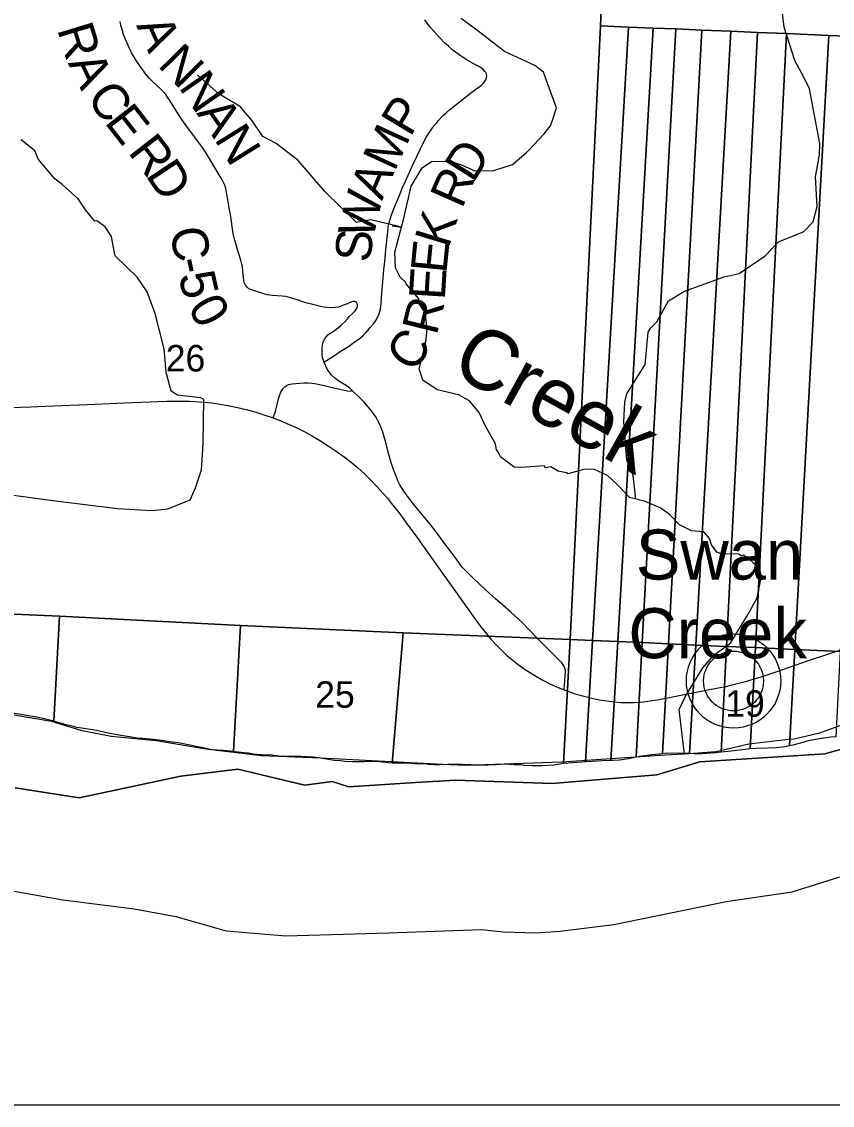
# Model space of a CAD drawing. Extents: x 396.2 to 468.4, y 232.6 to 279.1.
# Drawn here: x 422.381 to 423.66, y 264.258 to 265.969 of the extents above; entities that cross this region are included whole.
import ezdxf

# ---------------------------------------------------------------- set-up
doc = ezdxf.new("R2010")
doc.units = 0
for name, color, linetype in [('GM_X_County_Road', 7, 'Continuous'), ('GM_X_County_Road_Text', 7, 'Continuous'), ('GM_X_Major_River', 7, 'Continuous'), ('GM_X_Minor_River', 7, 'Continuous'), ('GM_X_Minor_River_Text', 7, 'Continuous'), ('GM_X_Section', 7, 'Continuous'), ('GM_X_Section_Text', 7, 'Continuous'), ('GM_X_State_Route', 7, 'Continuous'), ('GM_X_Township', 7, 'Continuous'), ('GM_X_Unincorporated', 7, 'Continuous'), ('GM_X_Unincorporated_Location', 7, 'Continuous'), ('GM_X_Unincorporated_Text', 7, 'Continuous'), ('SH_Cut_Line', 7, 'Continuous'), ('TX_P_1', 7, 'Continuous')]:
    doc.layers.add(name, color=color, linetype=linetype)

msp = doc.modelspace()

# ---------------------------------------------------------------- linework, layer by layer
at = {"layer": 'GM_X_County_Road'}
for points in [[(422.8581, 265.4314), (422.8568, 265.4354), (422.8558, 265.4388), (422.8553, 265.443), (422.8552, 265.4474), (422.8552, 265.4524), (422.8558, 265.4587), (422.8569, 265.4626), (422.8578, 265.4653), (422.8598, 265.469), (422.8621, 265.4718), (422.8642, 265.4742), (422.8673, 265.4766), (422.8727, 265.4804), (422.8774, 265.4833), (422.8809, 265.4858), (422.8851, 265.4894), (422.8907, 265.4949), (422.8953, 265.4998), (422.8979, 265.5032), (422.9024, 265.5074), (422.9066, 265.5115), (422.9089, 265.5143), (422.9103, 265.5169), (422.9108, 265.5191), (422.9109, 265.5207), (422.9107, 265.5225), (422.91, 265.5242), (422.909, 265.5255), (422.9076, 265.5265), (422.9059, 265.5271), (422.904, 265.5271), (422.9017, 265.5265), (422.8986, 265.5253), (422.8935, 265.5227), (422.8874, 265.5204), (422.8808, 265.5182), (422.8749, 265.5173), (422.8684, 265.5168), (422.8584, 265.5179), (422.8523, 265.519), (422.8402, 265.522), (422.8295, 265.525), (422.8139, 265.53), (422.8053, 265.5329), (422.7978, 265.5348), (422.7918, 265.5356), (422.7765, 265.5364), (422.7722, 265.5368), (422.7682, 265.5376), (422.7632, 265.539), (422.7481, 265.5438), (422.7426, 265.5457), (422.7394, 265.5472), (422.7365, 265.5496), (422.7342, 265.5525), (422.7331, 265.5548), (422.732, 265.5572), (422.7313, 265.5602), (422.7307, 265.5653), (422.7299, 265.5745), (422.7291, 265.5823), (422.7284, 265.5858), (422.7267, 265.5922), (422.7225, 265.6056), (422.7182, 265.62), (422.7162, 265.6277), (422.7148, 265.6345), (422.7133, 265.6447), (422.7113, 265.6581), (422.7103, 265.6641), (422.7083, 265.6743), (422.707, 265.6812), (422.7057, 265.6905), (422.7043, 265.6995), (422.703, 265.7055), (422.7014, 265.7104), (422.6999, 265.7138), (422.6966, 265.7203), (422.6854, 265.7389), (422.676, 265.7543), (422.6708, 265.7627), (422.6661, 265.7701), (422.6599, 265.7786), (422.654, 265.7865), (422.6424, 265.8018), (422.6364, 265.8105), (422.6317, 265.8175), (422.6174, 265.8399), (422.6137, 265.8456), (422.611, 265.8496), (422.6081, 265.8538), (422.6041, 265.8584), (422.5997, 265.8627), (422.588, 265.8738), (422.5828, 265.8791), (422.577, 265.8858), (422.5714, 265.893), (422.5635, 265.9044), (422.5582, 265.9127), (422.5544, 265.9196), (422.5494, 265.9298), (422.5447, 265.9406), (422.5417, 265.9486), (422.5392, 265.9565), (422.5374, 265.9628), (422.5361, 265.969)], [(422.8581, 265.4314), (422.859, 265.432), (422.8619, 265.4337), (422.8727, 265.4407), (422.8853, 265.4489), (422.8964, 265.4562), (422.9035, 265.461), (422.9089, 265.4648), (422.9133, 265.468), (422.9161, 265.4703), (422.9201, 265.474), (422.9233, 265.4772), (422.9273, 265.4813), (422.931, 265.4858), (422.9354, 265.4913), (422.9399, 265.4972), (422.9427, 265.5026), (422.9449, 265.5074), (422.946, 265.511), (422.9469, 265.5149), (422.9477, 265.5195), (422.948, 265.5232), (422.9487, 265.5331), (422.9495, 265.5462), (422.9513, 265.5639), (422.9526, 265.5773), (422.9538, 265.5897), (422.9552, 265.6035), (422.9575, 265.6278), (422.9585, 265.6369), (422.9594, 265.6432), (422.96, 265.6473), (422.9609, 265.6512), (422.9636, 265.6607), (422.9669, 265.6705), (422.9716, 265.682), (422.9775, 265.6959), (422.9792, 265.6999), (422.9821, 265.7067), (422.9867, 265.7169), (422.9977, 265.7415), (423.005, 265.757), (423.0103, 265.768), (423.0184, 265.7842), (423.0226, 265.7913), (423.0279, 265.7994), (423.032, 265.8048), (423.0348, 265.808), (423.0387, 265.8128), (423.0434, 265.8181), (423.0467, 265.8213), (423.0506, 265.825), (423.0563, 265.8298), (423.0601, 265.8329), (423.0644, 265.8364), (423.0706, 265.8413), (423.0844, 265.8521), (423.0934, 265.8588), (423.1021, 265.8653), (423.1065, 265.8687), (423.1091, 265.8709), (423.1114, 265.8736), (423.1133, 265.8769), (423.1144, 265.8798), (423.1148, 265.883), (423.1143, 265.8861), (423.1132, 265.8883), (423.112, 265.89), (423.1097, 265.8926), (423.1067, 265.8953), (423.1032, 265.8976), (423.0973, 265.9008), (423.0837, 265.9081), (423.0729, 265.9151), (423.062, 265.923), (423.0542, 265.9299), (423.0486, 265.9348), (423.0398, 265.9443), (423.0267, 265.9591), (423.021, 265.9665), (423.0172, 265.9715)], [(422.9025, 265.3864), (422.9008, 265.3879), (422.8985, 265.3901), (422.8936, 265.3937), (422.891, 265.3953), (422.8856, 265.3984), (422.8799, 265.4022), (422.8746, 265.4065), (422.87, 265.4108), (422.8661, 265.4158), (422.8632, 265.4204), (422.8614, 265.4238), (422.8599, 265.4268), (422.8587, 265.4299), (422.8581, 265.4314)], [(422.7779, 265.3431), (422.7818, 265.3555), (422.7842, 265.3646), (422.7864, 265.3736), (422.7877, 265.3783), (422.7887, 265.3813), (422.7897, 265.3838), (422.7913, 265.3867), (422.7931, 265.3892), (422.7946, 265.3909), (422.7967, 265.3928), (422.7987, 265.3943), (422.8018, 265.3958), (422.8046, 265.3966), (422.8078, 265.3972), (422.8134, 265.3978), (422.8196, 265.3982), (422.8264, 265.3985), (422.8329, 265.3984), (422.8391, 265.3979), (422.8434, 265.3973), (422.8484, 265.3965), (422.8535, 265.3954), (422.8582, 265.3945), (422.8664, 265.3923), (422.8803, 265.3891), (422.8899, 265.3868), (422.8953, 265.3859), (422.8992, 265.3857), (422.9025, 265.3864)], [(423.237, 264.9139), (423.2377, 264.9222), (423.2382, 264.9278), (423.2388, 264.9362), (423.2389, 264.9406), (423.2389, 264.9438), (423.2386, 264.9465), (423.2379, 264.9489), (423.237, 264.951), (423.2355, 264.9535), (423.2337, 264.9559), (423.2316, 264.9582), (423.2267, 264.9635), (423.2128, 264.9772), (423.1965, 264.9937), (423.1809, 265.0097), (423.1715, 265.0191), (423.1639, 265.0266), (423.1526, 265.0365), (423.1398, 265.0481), (423.1288, 265.0579), (423.1194, 265.0663), (423.0938, 265.0899), (423.0822, 265.1012), (423.0761, 265.1079), (423.073, 265.1118), (423.0679, 265.1187), (423.0574, 265.1329), (423.0472, 265.1466), (423.0386, 265.1582), (423.0329, 265.1658), (423.0269, 265.1735), (423.0201, 265.1816), (422.9992, 265.2072), (422.9928, 265.2156), (422.9865, 265.224), (422.9838, 265.2278), (422.9801, 265.2335), (422.9779, 265.2374), (422.9746, 265.244), (422.9717, 265.2512), (422.9688, 265.2589), (422.9652, 265.2695), (422.9625, 265.2779), (422.9593, 265.2894), (422.9574, 265.2961), (422.9548, 265.3058), (422.9527, 265.3133), (422.9506, 265.3206), (422.9487, 265.3262), (422.9469, 265.3303), (422.945, 265.3347), (422.9427, 265.3393), (422.9396, 265.3447), (422.9368, 265.349), (422.9329, 265.3546), (422.9274, 265.3615), (422.9207, 265.3688), (422.9172, 265.3723), (422.914, 265.3753), (422.9118, 265.3773), (422.9061, 265.3827), (422.9046, 265.3843), (422.9038, 265.3851), (422.9025, 265.3864)]]:
    msp.add_lwpolyline(points, dxfattribs=at)
at = {"layer": 'GM_X_Major_River'}
msp.add_line((423.4267, 264.8125), (423.3956, 264.8109), dxfattribs=at)
for points in [[(423.3956, 264.8109), (423.2334, 264.7997), (423.0818, 264.7946), (423.0454, 264.7964), (422.8525, 264.806), (422.7592, 264.8101), (422.6717, 264.8202), (422.5932, 264.8337), (422.5219, 264.8405), (422.4764, 264.8495), (422.4279, 264.8639), (422.3377, 264.8793)], [(423.7003, 264.8675), (423.64, 264.8458), (423.6002, 264.8363), (423.5908, 264.8355), (423.5282, 264.8282), (423.4771, 264.8164), (423.4267, 264.8125)], [(422.2739, 264.6133), (422.446, 264.5828), (422.5586, 264.5685), (422.6242, 264.5561), (422.7038, 264.5338), (422.7975, 264.5259), (422.9604, 264.5303), (422.9741, 264.5311), (423.1071, 264.5355), (423.1401, 264.5321), (423.1935, 264.5307), (423.2303, 264.533), (423.3156, 264.5437), (423.4925, 264.58), (423.5967, 264.5953), (423.6721, 264.619)]]:
    msp.add_lwpolyline(points, dxfattribs=at)
at = {"layer": 'GM_X_Minor_River'}
for points in [[(423.35, 265.2151), (423.3458, 265.2521), (423.3359, 265.2763), (423.3314, 265.3369), (423.3327, 265.3683), (423.3361, 265.3811), (423.3647, 265.4273), (423.3697, 265.4784), (423.374, 265.4855), (423.3834, 265.4947), (423.4014, 265.5279), (423.4268, 265.5434), (423.4895, 265.5661), (423.5131, 265.571), (423.554, 265.5989), (423.5751, 265.6214), (423.608, 265.6341), (423.6153, 265.6376), (423.6297, 265.6527), (423.6365, 265.6768), (423.6334, 265.7236), (423.6401, 265.7583), (423.6403, 265.7762), (423.624, 265.8629), (423.6151, 265.881), (423.6012, 265.9073), (423.5842, 265.9598), (423.5773, 266.0178)], [(423.4573, 265.1633), (423.438, 265.1649), (423.4191, 265.1743), (423.4029, 265.1914), (423.3885, 265.2012), (423.365, 265.2114), (423.3401, 265.2175), (423.3234, 265.2353), (423.3204, 265.2383), (423.3056, 265.2523), (423.2848, 265.2618), (423.2697, 265.2625), (423.2433, 265.2549), (423.2406, 265.2568), (423.2274, 265.259), (423.2157, 265.2662), (423.2104, 265.2647), (423.2077, 265.2639), (423.2055, 265.2677), (423.1696, 265.2649), (423.1582, 265.2653), (423.1363, 265.2816), (423.1329, 265.2899), (423.1302, 265.293), (423.1287, 265.3021), (423.1124, 265.3313), (423.1029, 265.3518), (423.0878, 265.3704), (423.07, 265.3795), (423.0364, 265.3878), (423.0137, 265.4029), (423.008, 265.4208), (423.0185, 265.4626), (423.0208, 265.4843), (423.0174, 265.5097), (423.0087, 265.523), (423.0075, 265.531), (422.9878, 265.5549), (422.9871, 265.5572), (422.978, 265.5655), (422.9708, 265.5803), (422.9696, 265.605), (422.984, 265.6586), (422.9956, 265.7088), (423.013, 265.7381), (423.0274, 265.748), (423.0576, 265.7485), (423.0761, 265.7424), (423.0958, 265.7334), (423.126, 265.7338), (423.1555, 265.7434), (423.177, 265.7617), (423.1812, 265.7659), (423.2054, 265.7914), (423.2152, 265.8043), (423.219, 265.815), (423.225, 265.8325), (423.214, 265.8625), (423.2041, 265.8891), (423.1909, 265.8997), (423.1429, 265.9216), (423.1032, 265.9519), (423.0744, 265.9739)], [(422.9655, 265.6466), (422.9802, 265.6445), (422.9321, 265.6557), (422.9093, 265.6515), (422.8594, 265.7005), (422.817, 265.7497), (422.7823, 265.7763), (422.7615, 265.7876), (422.7452, 265.8116), (422.7255, 265.8346), (422.6924, 265.8543), (422.6582, 265.885)], [(422.3088, 265.2292), (422.4298, 265.2127), (422.5323, 265.2004), (422.5871, 265.1971), (422.6109, 265.1998), (422.6139, 265.2006), (422.6468, 265.214), (422.6551, 265.233), (422.6645, 265.2615), (422.6671, 265.3022), (422.6682, 265.3725), (422.6637, 265.3751), (422.627, 265.3789), (422.6168, 265.3853), (422.6088, 265.4153), (422.6057, 265.4522), (422.5917, 265.508), (422.5788, 265.5422), (422.5633, 265.5653), (422.5289, 265.5987), (422.5277, 265.6006), (422.5224, 265.6295), (422.5126, 265.645), (422.4993, 265.6545), (422.4963, 265.6537), (422.4816, 265.6719), (422.4702, 265.689), (422.4449, 265.7114), (422.4331, 265.7205), (422.4074, 265.7512), (422.4017, 265.7649), (422.3798, 265.7823)], [(423.5, 264.9888), (423.5274, 265.0336), (423.5413, 265.0594), (423.5481, 265.0906), (423.5436, 265.1066), (423.5273, 265.1217), (423.5193, 265.1267), (423.5159, 265.1255), (423.5125, 265.1282), (423.4846, 265.1289), (423.4781, 265.1311), (423.4694, 265.1429), (423.4664, 265.1528), (423.4573, 265.1633)], [(423.4267, 264.8125), (423.4183, 264.8832), (423.4281, 264.903), (423.456, 264.949), (423.4734, 264.9685), (423.4998, 264.9881)]]:
    msp.add_lwpolyline(points, dxfattribs=at)
at = {"layer": 'GM_X_Section'}
for points in [[(422.382, 266.0626), (422.4978, 266.0581), (422.6167, 266.0532), (422.729, 266.048), (422.8437, 266.0426), (422.9516, 266.0386), (423.065, 266.034), (423.1841, 266.029), (423.2972, 266.0233), (423.2945, 265.962), (423.2463, 264.9936), (422.9829, 265.0038), (422.7263, 265.0156), (422.4405, 265.0302), (422.2012, 265.0407), (422.2722, 266.0688)], [(424.307, 265.9824), (424.3036, 265.92), (424.2498, 265.9223), (424.1725, 265.9255), (424.0858, 265.9291), (424.009, 265.9323), (423.9355, 265.9353), (423.8676, 265.9382), (423.7934, 265.9413), (423.724, 265.9441), (423.6546, 265.947), (423.588, 265.9498), (423.5421, 265.9517), (423.5001, 265.9535), (423.4544, 265.9554), (423.4134, 265.9571), (423.3774, 265.9586), (423.3387, 265.9602), (423.2945, 265.962), (423.2972, 266.0233)], [(423.2945, 265.962), (423.3387, 265.9602), (423.2819, 264.992), (423.2463, 264.9936)], [(423.3387, 265.9602), (423.3774, 265.9586), (423.3215, 264.9902), (423.2819, 264.992)], [(423.3774, 265.9586), (423.4134, 265.9571), (423.3603, 264.9885), (423.3215, 264.9902)], [(423.4134, 265.9571), (423.4544, 265.9554), (423.4014, 264.9867), (423.3603, 264.9885)], [(423.4544, 265.9554), (423.5001, 265.9535), (423.4448, 264.9847), (423.4014, 264.9867)], [(423.5001, 265.9535), (423.5421, 265.9517), (423.493, 264.9826), (423.4448, 264.9847)], [(423.5421, 265.9517), (423.588, 265.9498), (423.5387, 264.9806), (423.493, 264.9826)], [(423.588, 265.9498), (423.6546, 265.947), (423.601, 264.9778), (423.5387, 264.9806)], [(423.6546, 265.947), (423.724, 265.9441), (423.6728, 264.9746), (423.601, 264.9778)], [(422.2012, 265.0407), (422.4405, 265.0302), (422.4314, 264.8644), (422.4188, 264.8679), (422.404, 264.8708), (422.3915, 264.8731), (422.3771, 264.8757), (422.3615, 264.8779), (422.3449, 264.8805), (422.3331, 264.882), (422.3278, 264.8819), (422.3179, 264.8838), (422.3016, 264.8864), (422.2872, 264.889), (422.2728, 264.8923), (422.2626, 264.8957), (422.2516, 264.8987), (422.2436, 264.9002), (422.2391, 264.9009), (422.2345, 264.9025), (422.2224, 264.9043), (422.2072, 264.9077), (422.1972, 264.9098)], [(422.4405, 265.0302), (422.7263, 265.0156), (422.7151, 264.8165), (422.6986, 264.8181), (422.6812, 264.8191), (422.6762, 264.8203), (422.6641, 264.8229), (422.6436, 264.8273), (422.6281, 264.8303), (422.6144, 264.8322), (422.5981, 264.8348), (422.583, 264.8362), (422.5723, 264.8373), (422.5625, 264.8377), (422.5572, 264.8388), (422.5481, 264.8403), (422.5375, 264.8417), (422.5227, 264.8447), (422.5079, 264.8477), (422.4996, 264.8496), (422.4889, 264.8514), (422.476, 264.8537), (422.4677, 264.8544), (422.4605, 264.8566), (422.4495, 264.8592), (422.4385, 264.8622), (422.4314, 264.8644)], [(422.7263, 265.0156), (422.9829, 265.0038), (422.9655, 264.7982), (422.9593, 264.7989), (422.9412, 264.8007), (422.9207, 264.8003), (422.9029, 264.8006), (422.8915, 264.8009), (422.8839, 264.802), (422.8741, 264.8024), (422.8619, 264.8046), (422.8491, 264.8068), (422.8407, 264.8076), (422.8316, 264.8083), (422.8218, 264.809), (422.8021, 264.809), (422.7873, 264.8093), (422.7759, 264.8108), (422.7592, 264.8115), (422.7456, 264.8125), (422.7384, 264.814), (422.7319, 264.8148), (422.7183, 264.8162), (422.7151, 264.8165)], [(422.9829, 265.0038), (423.2463, 264.9936), (423.2358, 264.7977), (423.23, 264.7969), (423.22, 264.7953), (423.2015, 264.7941), (423.1863, 264.794), (423.1738, 264.7947), (423.1693, 264.7955), (423.1579, 264.7958), (423.1431, 264.7965), (423.1295, 264.7957), (423.117, 264.7949), (423.1033, 264.7945), (423.0897, 264.7956), (423.0761, 264.7963), (423.0658, 264.7966), (423.0529, 264.7962), (423.0404, 264.7958), (423.0313, 264.7957), (423.023, 264.7961), (423.0158, 264.7972), (423.0101, 264.7972), (423.0007, 264.7971), (422.9908, 264.7982), (422.973, 264.7982), (422.9655, 264.7982)], [(423.2819, 264.992), (423.2706, 264.8002), (423.2655, 264.8), (423.25, 264.7988), (423.2358, 264.7977), (423.2463, 264.9936)], [(423.3215, 264.9902), (423.3107, 264.8023), (423.2969, 264.802), (423.281, 264.8008), (423.2706, 264.8002), (423.2819, 264.992)], [(423.3603, 264.9885), (423.3504, 264.8075), (423.3386, 264.8051), (423.3242, 264.8028), (423.3136, 264.8024), (423.3107, 264.8023), (423.3215, 264.9902)], [(423.4014, 264.9867), (423.3919, 264.8132), (423.3757, 264.8113), (423.3594, 264.8094), (423.3504, 264.8075), (423.3603, 264.9885)], [(423.4448, 264.9847), (423.435, 264.8135), (423.3992, 264.8141), (423.3919, 264.8132), (423.4014, 264.9867)], [(423.493, 264.9826), (423.4845, 264.8156), (423.4757, 264.8147), (423.4469, 264.8123), (423.4416, 264.8131), (423.435, 264.8135), (423.4448, 264.9847)], [(423.5387, 264.9806), (423.5306, 264.8209), (423.5144, 264.8186), (423.4951, 264.8167), (423.4845, 264.8156), (423.493, 264.9826)], [(423.601, 264.9778), (423.5926, 264.8254), (423.5852, 264.8238), (423.5716, 264.8226), (423.5579, 264.8218), (423.5397, 264.8214), (423.5306, 264.8209), (423.5387, 264.9806)], [(423.6728, 264.9746), (423.6657, 264.8399), (423.6579, 264.8392), (423.6424, 264.8373), (423.6223, 264.8334), (423.6102, 264.83), (423.5981, 264.8265), (423.5926, 264.8254), (423.601, 264.9778)]]:
    msp.add_lwpolyline(points, close=True, dxfattribs=at)
at = {"layer": 'GM_X_State_Route'}
for points in [[(422.3626, 265.3594), (422.3952, 265.3607), (422.4309, 265.3622), (422.4843, 265.3646), (422.555, 265.3676), (422.5836, 265.3688), (422.6092, 265.3697), (422.624, 265.3699), (422.6368, 265.3699), (422.6459, 265.3697), (422.6549, 265.3693), (422.6679, 265.3683), (422.6806, 265.3669), (422.6943, 265.3649), (422.7064, 265.3628), (422.7216, 265.3597), (422.735, 265.3565), (422.7488, 265.3527), (422.763, 265.3482), (422.7779, 265.3431), (422.79, 265.3385), (422.8032, 265.3329), (422.815, 265.3274), (422.8278, 265.321), (422.8399, 265.3144), (422.8522, 265.3072), (422.8648, 265.2992), (422.8772, 265.2908), (422.8898, 265.2816), (422.9006, 265.2732), (422.9111, 265.2644), (422.9217, 265.2547), (422.9311, 265.2456), (422.9414, 265.2349), (422.9515, 265.2238), (422.958, 265.2163), (422.9663, 265.2062), (422.9758, 265.1938), (422.9839, 265.1828), (422.9905, 265.1738), (422.9972, 265.1648), (423.006, 265.1528), (423.0226, 265.1295), (423.0495, 265.0915), (423.0874, 265.0383), (423.1034, 265.0162), (423.1121, 265.0049), (423.1217, 264.9935), (423.1296, 264.9848), (423.1379, 264.9765), (423.146, 264.9689), (423.1564, 264.9601), (423.1643, 264.954), (423.1738, 264.9472), (423.1755, 264.9461)], [(423.1755, 264.9461), (423.1836, 264.9407), (423.1932, 264.9349), (423.2035, 264.9293), (423.2146, 264.9237), (423.2276, 264.9178), (423.237, 264.9139), (423.2472, 264.9102), (423.256, 264.9073), (423.2679, 264.9039), (423.2806, 264.9008), (423.2921, 264.8984), (423.3043, 264.8964), (423.3154, 264.8951), (423.3265, 264.8942), (423.3341, 264.8939), (423.3406, 264.8939), (423.3475, 264.8942), (423.355, 264.8947), (423.362, 264.8953), (423.3691, 264.8961), (423.3838, 264.8984), (423.4082, 264.903), (423.4613, 264.9133), (423.4802, 264.917), (423.4919, 264.9195), (423.5035, 264.9222), (423.5147, 264.9249), (423.5251, 264.9278), (423.5368, 264.9312), (423.548, 264.9346), (423.5715, 264.9426), (423.6225, 264.9604), (423.6529, 264.9705)], [(423.6529, 264.9705), (423.6909, 264.9831)]]:
    msp.add_lwpolyline(points, dxfattribs=at)
at = {"layer": 'GM_X_Township'}
msp.add_lwpolyline([(424.5226, 265.269), (424.3974, 265.1684), (424.2806, 265.0379), (424.1978, 265.0046), (424.0414, 264.926), (423.9438, 264.8962), (423.6485, 264.813), (423.4509, 264.8004), (423.3832, 264.7796), (423.2178, 264.7664), (423.0657, 264.7713), (423.0026, 264.7679), (422.8972, 264.7611), (422.871, 264.7692), (422.8275, 264.7637), (422.7219, 264.7888), (422.6322, 264.7777), (422.4717, 264.7433), (422.3706, 264.7592)], dxfattribs=at)
at = {"layer": 'GM_X_Unincorporated'}
for radius in [0.0744, 0.0472]:
    msp.add_circle((423.5043, 264.928), radius, dxfattribs=at)
at = {"layer": 'GM_X_Unincorporated_Location'}
msp.add_line((423.5043, 264.928), (423.5043, 264.928), dxfattribs=at)
at = {"layer": 'SH_Cut_Line'}
msp.add_lwpolyline([(422.3706, 264.7592), (422.4717, 264.7433), (422.6322, 264.7777), (422.7219, 264.7888), (422.8275, 264.7637), (422.871, 264.7692), (422.8972, 264.7611), (423.0026, 264.7679), (423.0657, 264.7713), (423.2178, 264.7664), (423.3832, 264.7796), (423.4509, 264.8004), (423.6485, 264.813), (423.9438, 264.8962), (424.0414, 264.926), (424.1978, 265.0046), (424.2806, 265.0379), (424.3974, 265.1684), (424.5226, 265.269)], dxfattribs=at)
at = {"layer": 'TX_P_1'}
msp.add_line((427.4513, 264.2582), (413.8513, 264.2582), dxfattribs=at)

# ---------------------------------------------------------------- texts
at = {"layer": 'GM_X_County_Road_Text'}
for s, rotation, p in [('R', 286.9005, (422.4365, 265.9569)), ('A', 294.0227, (422.5613, 265.9628)), ('N', 314.5183, (422.5941, 265.8989)), ('A', 295.826, (422.4536, 265.9033)), ('N', 304.9086, (422.6275, 265.8652)), ('C', 306.8329, (422.4816, 265.8481)), ('P', 58.982, (422.994, 265.7852)), ('E', 308.0682, (422.5104, 265.8097)), ('A', 304.4074, (422.6561, 265.8243)), ('N', 301.8621, (422.684, 265.7836)), ('R', 307.9948, (422.5474, 265.7625)), ('M', 65.3393, (422.9691, 265.7307)), ('D', 57.8154, (423.0934, 265.7127)), ('D', 303.5294, (422.5754, 265.7266)), ('A', 66.6574, (422.9494, 265.6851)), ('R', 66.1921, (423.0755, 265.672)), ('W', 76.3164, (422.9347, 265.6235)), ('K', 73.1624, (423.0547, 265.6098)), ('C', 279.615, (422.6146, 265.6406)), ('S', 83.9975, (422.931, 265.5874)), ('E', 84.3037, (423.051, 265.5703)), ('-', 282.552, (422.623, 265.5915)), ('5', 282.8033, (422.6281, 265.5685)), ('E', 86.4866, (423.0485, 265.5285)), ('0', 298.7505, (422.642, 265.5182)), ('R', 76.1921, (423.0357, 265.4722)), ('C', 53.8639, (422.998, 265.4127))]:
    msp.add_text(s, height=0.0568, rotation=rotation, dxfattribs=at).set_placement(p)
at = {"layer": 'GM_X_Minor_River_Text'}
msp.add_text('Creek', height=0.09469, rotation=330.9989, dxfattribs=at).set_placement((423.0545, 265.4161))
at = {"layer": 'GM_X_Section_Text'}
for s, p in [('26', (422.6083, 265.4165)), ('25', (422.8442, 264.8857)), ('19', (423.4913, 264.8715))]:
    msp.add_text(s, height=0.04186, rotation=0, dxfattribs=at).set_placement(p)
at = {"layer": 'GM_X_Unincorporated_Text'}
for s, p in [('Swan', (423.35, 265.0881)), ('Creek', (423.3383, 264.9639))]:
    msp.add_text(s, height=0.07898, rotation=0, dxfattribs=at).set_placement(p)

doc.saveas('drawing.dxf')
